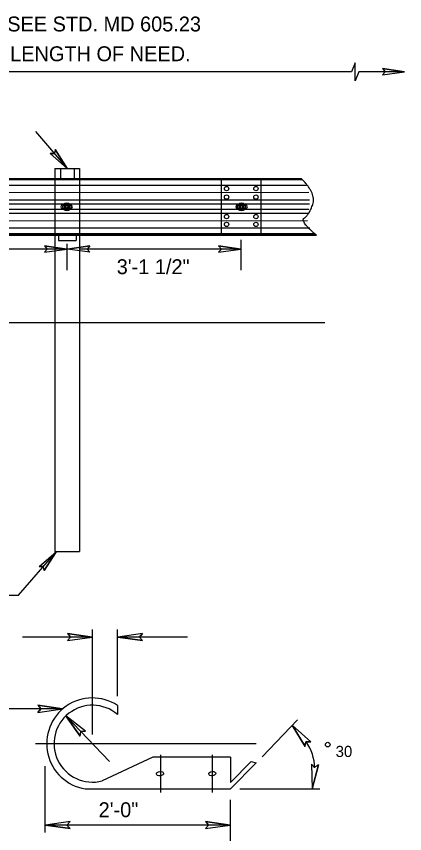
# Model space of a CAD drawing. Extents: x 12.2 to 54.5, y -7.8 to 16.1.
# Drawn here: x 17.698 to 19.261, y 12.576 to 15.871 of the extents above; entities that cross this region are included whole.
import ezdxf

# ---------------------------------------------------------------- set-up
doc = ezdxf.new("R2010")
doc.units = 0
for name, color, linetype in [('BORD-LINE', 7, 'Continuous'), ('DETL-DIMS', 7, 'Continuous'), ('DETL-LINE', 7, 'Continuous'), ('DETL-NOTE', 7, 'Continuous')]:
    doc.layers.add(name, color=color, linetype=linetype)

msp = doc.modelspace()

# ---------------------------------------------------------------- linework, layer by layer
at = {"layer": 'BORD-LINE'}
for p, q in [((17.8531, 15.258), (17.8531, 15.2157)), ((17.8531, 15.258), (17.952, 15.258)), ((17.8753, 15.258), (17.8753, 15.2174)), ((17.9313, 15.258), (17.9313, 15.2162)), ((17.9516, 15.258), (17.9516, 15.2174)), ((17.8531, 15.2247), (17.8531, 14.9901)), ((17.9515, 15.2247), (17.9515, 14.9901)), ((18.8504, 15.2118), (16.7003, 15.2118)), ((18.8462, 15.2162), (16.701, 15.216)), ((18.8758, 15.1602), (16.6898, 15.1599)), ((18.8663, 15.1891), (16.6947, 15.1888)), ((18.8788, 15.13), (16.6823, 15.1297)), ((18.8752, 15.0928), (16.6747, 15.0925)), ((18.8785, 15.1135), (16.6793, 15.1131)), ((17.9167, 15.1102), (17.8839, 15.1102)), ((17.8839, 15.0961), (17.9167, 15.0961)), ((17.8905, 15.1089), (17.8905, 15.0974)), ((17.9116, 15.0974), (17.9116, 15.1089)), ((18.6213, 15.1098), (18.5885, 15.1098)), ((18.5885, 15.0958), (18.6213, 15.0958)), ((18.5938, 15.1086), (18.5938, 15.0971)), ((18.6149, 15.0971), (18.6149, 15.1086)), ((18.8725, 15.0763), (16.6708, 15.076)), ((18.8704, 15.046), (16.6643, 15.0457)), ((18.8992, 14.9945), (16.6539, 14.9942)), ((18.8799, 15.0172), (16.6586, 15.0169)), ((18.906, 14.988), (16.6522, 14.9875)), ((18.9034, 14.9903), (16.6525, 14.99)), ((17.8531, 14.9901), (17.8531, 14.6373)), ((17.8673, 14.9879), (17.8673, 14.9678)), ((17.8673, 14.9678), (17.9388, 14.9678)), ((17.9387, 14.9877), (17.9387, 14.9678)), ((17.9515, 14.9901), (17.9515, 14.6369)), ((12.3965, 14.6369), (18.9405, 14.6369)), ((17.8531, 14.636), (17.8531, 13.713)), ((17.9515, 14.6369), (17.9515, 13.713)), ((17.8531, 13.713), (17.9515, 13.713))]:
    msp.add_line(p, q, dxfattribs=at)
for points in [[(17.901, 15.109), (17.8994, 15.1089), (17.8978, 15.1087), (17.8964, 15.1082), (17.895, 15.1077), (17.8939, 15.1069), (17.8929, 15.1061), (17.8922, 15.1052), (17.8918, 15.1042), (17.8917, 15.1032), (17.8918, 15.1022), (17.8922, 15.1012), (17.8929, 15.1002), (17.8939, 15.0994), (17.895, 15.0987), (17.8964, 15.0981), (17.8978, 15.0977), (17.8994, 15.0974), (17.901, 15.0973)], [(17.901, 15.0973), (17.9027, 15.0974), (17.9042, 15.0977), (17.9057, 15.0981), (17.9071, 15.0987), (17.9082, 15.0994), (17.9091, 15.1002), (17.9098, 15.1012), (17.9103, 15.1022), (17.9104, 15.1032), (17.9103, 15.1042), (17.9098, 15.1052), (17.9091, 15.1061), (17.9082, 15.1069), (17.9071, 15.1077), (17.9057, 15.1082), (17.9042, 15.1087), (17.9027, 15.1089), (17.901, 15.109)], [(18.6043, 15.1087), (18.6027, 15.1086), (18.6011, 15.1083), (18.5996, 15.1079), (18.5983, 15.1073), (18.5972, 15.1066), (18.5962, 15.1057), (18.5955, 15.1048), (18.5951, 15.1038), (18.595, 15.1028), (18.5951, 15.1018), (18.5955, 15.1008), (18.5962, 15.0999), (18.5972, 15.0991), (18.5983, 15.0983), (18.5996, 15.0978), (18.6011, 15.0973), (18.6027, 15.0971), (18.6043, 15.097)], [(18.6043, 15.097), (18.606, 15.0971), (18.6075, 15.0973), (18.609, 15.0978), (18.6103, 15.0983), (18.6115, 15.0991), (18.6124, 15.0999), (18.6131, 15.1008), (18.6136, 15.1018), (18.6137, 15.1028), (18.6136, 15.1038), (18.6131, 15.1048), (18.6124, 15.1057), (18.6115, 15.1066), (18.6103, 15.1073), (18.609, 15.1079), (18.6075, 15.1083), (18.606, 15.1086), (18.6043, 15.1087)]]:
    msp.add_lwpolyline(points, dxfattribs=at)
for centre, radius in [((17.901, 15.1032), 0.0164), ((17.901, 15.1032), 0.00702), ((17.901, 15.1032), 0.00614), ((17.901, 15.1032), 0.00585), ((17.901, 15.1032), 0.00498), ((18.6043, 15.1028), 0.0164), ((18.6043, 15.1028), 0.00702), ((18.6043, 15.1028), 0.00614), ((18.6043, 15.1028), 0.00585), ((18.6043, 15.1028), 0.00498)]:
    msp.add_circle(centre, radius, dxfattribs=at)
for centre, radius, start, end in [((17.8839, 15.1032), 0.00702, 90.0039, 269.9961), ((17.901, 15.1032), 0.012, 28.6537, 151.3463), ((17.901, 15.1032), 0.012, 208.653, 331.347), ((17.901, 15.1032), 0.00879, 120.0035, 179.9936), ((17.901, 15.1032), 0.00879, 180.0054, 239.9976), ((17.901, 15.1032), 0.00878, 59.9996, 120.0004), ((17.901, 15.1032), 0.00878, 239.9975, 300.0025), ((17.901, 15.1032), 0.00643, 57.8729, 122.1271), ((17.901, 15.1032), 0.00643, 237.8729, 302.1271), ((17.901, 15.1032), 0.00879, 0.0064, 59.9965), ((17.901, 15.1032), 0.00879, 300.0024, 359.9946), ((17.9167, 15.1032), 0.00702, 270.0039, 89.9961), ((18.5885, 15.1028), 0.00702, 90.0039, 269.9961), ((18.6043, 15.1028), 0.012, 28.6537, 151.3463), ((18.6043, 15.1028), 0.012, 208.653, 331.347), ((18.6043, 15.1028), 0.00879, 120.0035, 179.9936), ((18.6043, 15.1028), 0.00879, 180.0054, 239.9976), ((18.6043, 15.1028), 0.00878, 59.9996, 120.0004), ((18.6043, 15.1028), 0.00878, 239.9975, 300.0025), ((18.6043, 15.1028), 0.00643, 57.8729, 122.1271), ((18.6043, 15.1028), 0.00643, 237.8729, 302.1271), ((18.6043, 15.1028), 0.00879, 0.0064, 59.9965), ((18.6043, 15.1028), 0.00879, 300.0024, 359.9946), ((18.6213, 15.1028), 0.00702, 270.0039, 89.9961)]:
    msp.add_arc(centre, radius, start, end, dxfattribs=at)
for points in [[(17.8923, 15.1082), (17.8929, 15.1086), (17.8944, 15.1095), (17.8959, 15.1103), (17.8966, 15.1108), (17.8966, 15.1108)], [(17.8923, 15.1082), (17.8923, 15.1078), (17.8923, 15.1068), (17.8923, 15.1051), (17.8923, 15.1038), (17.8923, 15.1032)], [(17.8923, 15.1032), (17.8923, 15.1031), (17.8923, 15.1023), (17.8923, 15.1009), (17.8923, 15.0993), (17.8923, 15.0984), (17.8923, 15.0981)], [(17.8966, 15.0956), (17.896, 15.0959), (17.8948, 15.0966), (17.8933, 15.0975), (17.8925, 15.098), (17.8923, 15.0981)], [(17.8966, 15.1108), (17.8973, 15.1111), (17.8985, 15.1118), (17.8999, 15.1127), (17.9008, 15.1132), (17.901, 15.1133)], [(17.901, 15.093), (17.9003, 15.0934), (17.8989, 15.0943), (17.8974, 15.0951), (17.8967, 15.0955), (17.8966, 15.0956)], [(17.901, 15.1133), (17.9017, 15.1129), (17.9032, 15.1121), (17.9046, 15.1112), (17.9054, 15.1108), (17.9054, 15.1108)], [(17.9054, 15.0956), (17.9048, 15.0952), (17.9036, 15.0945), (17.9021, 15.0937), (17.9013, 15.0932), (17.901, 15.093)], [(17.9054, 15.1108), (17.906, 15.1104), (17.9073, 15.1097), (17.9087, 15.1089), (17.9096, 15.1084), (17.9098, 15.1082)], [(17.9098, 15.0981), (17.9091, 15.0977), (17.9077, 15.0969), (17.9062, 15.096), (17.9054, 15.0956), (17.9054, 15.0956)], [(17.9098, 15.1082), (17.9098, 15.1078), (17.9098, 15.1068), (17.9098, 15.1051), (17.9098, 15.1038), (17.9098, 15.1032)], [(17.9098, 15.1032), (17.9098, 15.1031), (17.9098, 15.1023), (17.9098, 15.1009), (17.9098, 15.0993), (17.9098, 15.0984), (17.9098, 15.0981)], [(18.5955, 15.1079), (18.5962, 15.1083), (18.5977, 15.1091), (18.5991, 15.11), (18.5999, 15.1104), (18.5999, 15.1104)], [(18.5955, 15.1079), (18.5955, 15.1075), (18.5955, 15.1064), (18.5955, 15.1047), (18.5955, 15.1035), (18.5955, 15.1028)], [(18.5955, 15.1028), (18.5955, 15.1027), (18.5955, 15.1019), (18.5955, 15.1006), (18.5955, 15.099), (18.5955, 15.098), (18.5955, 15.0978)], [(18.5999, 15.0952), (18.5993, 15.0956), (18.5981, 15.0963), (18.5966, 15.0971), (18.5958, 15.0976), (18.5955, 15.0978)], [(18.5999, 15.1104), (18.6005, 15.1108), (18.6018, 15.1115), (18.6032, 15.1123), (18.6041, 15.1128), (18.6043, 15.113)], [(18.6043, 15.0927), (18.6036, 15.0931), (18.6022, 15.0939), (18.6007, 15.0948), (18.6, 15.0952), (18.5999, 15.0952)], [(18.6043, 15.113), (18.605, 15.1126), (18.6065, 15.1117), (18.6079, 15.1109), (18.6087, 15.1104), (18.6087, 15.1104)], [(18.6087, 15.0952), (18.6081, 15.0949), (18.6069, 15.0942), (18.6054, 15.0933), (18.6046, 15.0928), (18.6043, 15.0927)], [(18.6087, 15.1104), (18.6093, 15.1101), (18.6106, 15.1094), (18.612, 15.1085), (18.6129, 15.108), (18.6131, 15.1079)], [(18.6131, 15.0978), (18.6124, 15.0974), (18.611, 15.0965), (18.6095, 15.0957), (18.6087, 15.0952), (18.6087, 15.0952)], [(18.6131, 15.1079), (18.6131, 15.1075), (18.6131, 15.1064), (18.6131, 15.1047), (18.6131, 15.1035), (18.6131, 15.1028)], [(18.6131, 15.1028), (18.6131, 15.1027), (18.6131, 15.1019), (18.6131, 15.1006), (18.6131, 15.099), (18.6131, 15.098), (18.6131, 15.0978)]]:
    msp.add_open_spline(points, degree=3, dxfattribs=at)
at = {"layer": 'DETL-DIMS'}
for p, q in [((19.1718, 15.6607), (19.2614, 15.6475)), ((19.1718, 15.6607), (19.1829, 15.6475)), ((19.0481, 15.6475), (15.8393, 15.6475)), ((19.2508, 15.6477), (19.0768, 15.6477)), ((19.1718, 15.6346), (19.2614, 15.6475)), ((19.1718, 15.6346), (19.1829, 15.6475)), ((17.7744, 15.4067), (17.9026, 15.258)), ((17.854, 15.3345), (17.8513, 15.3175)), ((17.854, 15.3345), (17.9026, 15.258)), ((17.8343, 15.3175), (17.9026, 15.258)), ((17.8343, 15.3175), (17.8513, 15.3175)), ((18.5234, 14.989), (18.5234, 15.2162)), ((18.6832, 14.988), (18.6832, 15.2152)), ((18.6038, 14.8471), (18.6038, 14.9706)), ((17.9011, 14.9328), (16.5563, 14.9328)), ((17.8115, 14.946), (17.9011, 14.9328)), ((17.8115, 14.946), (17.8226, 14.9328)), ((17.8115, 14.9199), (17.9011, 14.9328)), ((17.8115, 14.9199), (17.8226, 14.9328)), ((17.903, 14.8471), (17.903, 14.9532)), ((17.9936, 14.946), (17.904, 14.9328)), ((17.9936, 14.9199), (17.904, 14.9328)), ((18.5841, 14.9328), (17.9563, 14.9328)), ((17.9936, 14.946), (17.9825, 14.9328)), ((17.9936, 14.9199), (17.9825, 14.9328)), ((18.5123, 14.946), (18.6019, 14.9328)), ((18.5123, 14.946), (18.5234, 14.9328)), ((18.5123, 14.9199), (18.6019, 14.9328)), ((18.5123, 14.9199), (18.5234, 14.9328)), ((17.707, 13.5375), (17.858, 13.7127)), ((17.7897, 13.6532), (17.858, 13.7127)), ((17.8095, 13.6362), (17.858, 13.7127)), ((17.7897, 13.6532), (17.8068, 13.6532)), ((17.8095, 13.6362), (17.8068, 13.6532)), ((17.5585, 13.5375), (17.707, 13.5375)), ((17.9038, 13.383), (18.0027, 13.3686)), ((17.9038, 13.383), (17.9162, 13.3686)), ((17.9038, 13.383), (18.0027, 13.3686)), ((17.9038, 13.383), (17.9162, 13.3686)), ((18.0045, 12.9761), (18.0045, 13.3986)), ((18.0045, 12.9761), (18.0045, 13.3986)), ((18.1058, 13.1306), (18.1058, 13.3986)), ((18.1058, 13.1306), (18.1058, 13.3986)), ((18.2057, 13.383), (18.1068, 13.3686)), ((18.2057, 13.383), (18.1068, 13.3686)), ((18.2057, 13.383), (18.1934, 13.3686)), ((18.2057, 13.383), (18.1934, 13.3686)), ((18.0027, 13.3686), (17.7225, 13.3686)), ((18.0027, 13.3686), (17.7225, 13.3686)), ((17.9038, 13.3542), (18.0027, 13.3686)), ((17.9038, 13.3542), (17.9162, 13.3686)), ((17.9038, 13.3542), (18.0027, 13.3686)), ((17.9038, 13.3542), (17.9162, 13.3686)), ((18.387, 13.3686), (18.1068, 13.3686)), ((18.2057, 13.3542), (18.1068, 13.3686)), ((18.387, 13.3686), (18.1068, 13.3686)), ((18.2057, 13.3542), (18.1068, 13.3686)), ((18.2057, 13.3542), (18.1934, 13.3686)), ((18.2057, 13.3542), (18.1934, 13.3686)), ((17.7845, 13.0935), (17.8835, 13.0791)), ((17.7845, 13.0935), (17.7971, 13.0791)), ((17.8835, 13.0791), (17.2601, 13.0791)), ((17.7845, 13.0647), (17.8835, 13.0791)), ((17.7845, 13.0647), (17.7971, 13.0791)), ((17.8975, 13.0507), (18.0726, 12.8672)), ((17.8975, 13.0507), (18.0726, 12.8672)), ((17.9552, 12.9692), (17.8975, 13.0507)), ((17.9762, 12.9891), (17.8975, 13.0507)), ((18.6878, 12.8862), (18.8294, 13.0344)), ((18.6878, 12.8862), (18.8294, 13.0344)), ((17.9552, 12.9692), (17.9571, 12.9881)), ((17.9762, 12.9891), (17.9571, 12.9881)), ((18.8612, 12.9277), (18.8087, 13.0127)), ((18.8834, 12.9464), (18.8087, 13.0127)), ((18.8612, 12.9277), (18.8087, 13.0127)), ((18.8834, 12.9464), (18.8087, 13.0127)), ((18.6639, 12.9386), (17.7751, 12.9386)), ((18.6639, 12.9386), (17.7751, 12.9386)), ((18.8612, 12.9277), (18.8642, 12.9466)), ((18.8612, 12.9277), (18.8642, 12.9466)), ((18.8834, 12.9464), (18.8642, 12.9466)), ((18.8834, 12.9464), (18.8642, 12.9466)), ((18.2781, 12.8932), (18.2781, 12.7415)), ((18.2781, 12.8932), (18.2781, 12.7415)), ((18.4868, 12.8932), (18.4868, 12.7415)), ((18.4868, 12.8932), (18.4868, 12.7415)), ((18.8859, 12.8561), (18.8894, 12.7565)), ((18.8859, 12.8561), (18.899, 12.8424)), ((18.8859, 12.8561), (18.8894, 12.7565)), ((18.8859, 12.8561), (18.899, 12.8424)), ((18.9147, 12.8531), (18.8894, 12.7565)), ((18.9147, 12.8531), (18.8894, 12.7565)), ((18.9147, 12.8531), (18.899, 12.8424)), ((18.9147, 12.8531), (18.899, 12.8424)), ((17.8124, 12.8486), (17.8124, 12.5804)), ((18.5974, 12.7565), (18.9194, 12.7565)), ((18.5974, 12.7565), (18.9194, 12.7565)), ((18.5583, 12.7121), (18.5583, 12.0215)), ((17.9139, 12.6248), (17.8151, 12.6104)), ((17.9139, 12.6248), (17.9015, 12.6104)), ((18.4595, 12.6248), (18.5583, 12.6104)), ((18.4595, 12.6248), (18.4719, 12.6104)), ((18.5583, 12.6104), (17.8151, 12.6104)), ((17.9139, 12.596), (17.8151, 12.6104)), ((17.9139, 12.596), (17.9015, 12.6104)), ((18.4595, 12.596), (18.5583, 12.6104)), ((18.4595, 12.596), (18.4719, 12.6104))]:
    msp.add_line(p, q, dxfattribs=at)
for points in [[(19.1718, 15.6346), (19.2614, 15.6475), (19.1718, 15.6607), (19.1829, 15.6475)], [(17.8343, 15.3175), (17.9026, 15.258), (17.854, 15.3345), (17.8513, 15.3175)], [(17.8115, 14.9199), (17.9011, 14.9328), (17.8115, 14.946), (17.8226, 14.9328)], [(17.9936, 14.9199), (17.904, 14.9328), (17.9936, 14.946), (17.9825, 14.9328)], [(18.5123, 14.9199), (18.6019, 14.9328), (18.5123, 14.946), (18.5234, 14.9328)], [(17.7897, 13.6532), (17.858, 13.7127), (17.8095, 13.6362), (17.8068, 13.6532)], [(17.9038, 13.3542), (18.0027, 13.3686), (17.9038, 13.383), (17.9162, 13.3686)], [(17.9038, 13.3542), (18.0027, 13.3686), (17.9038, 13.383), (17.9162, 13.3686)], [(18.2057, 13.383), (18.1068, 13.3686), (18.2057, 13.3542), (18.1934, 13.3686)], [(18.2057, 13.383), (18.1068, 13.3686), (18.2057, 13.3542), (18.1934, 13.3686)], [(17.7845, 13.0647), (17.8835, 13.0791), (17.7845, 13.0935), (17.7971, 13.0791)], [(17.9762, 12.9891), (17.8975, 13.0507), (17.9552, 12.9692), (17.9571, 12.9881)], [(18.8834, 12.9464), (18.8087, 13.0127), (18.8612, 12.9277), (18.8642, 12.9466)], [(18.8834, 12.9464), (18.8087, 13.0127), (18.8612, 12.9277), (18.8642, 12.9466)], [(18.8859, 12.8561), (18.8894, 12.7565), (18.9147, 12.8531), (18.899, 12.8424)], [(18.8859, 12.8561), (18.8894, 12.7565), (18.9147, 12.8531), (18.899, 12.8424)], [(17.9139, 12.6248), (17.8151, 12.6104), (17.9139, 12.596), (17.9015, 12.6104)], [(18.4595, 12.596), (18.5583, 12.6104), (18.4595, 12.6248), (18.4719, 12.6104)]]:
    msp.add_lwpolyline(points, close=True, dxfattribs=at)
msp.add_arc((18.712, 12.8382), 0.1871, 0.8426, 35.4564, dxfattribs=at)
msp.add_arc((18.712, 12.8382), 0.1871, 0.8426, 35.4564, dxfattribs=at)
at = {"layer": 'DETL-LINE'}
for p, q in [((19.0626, 15.6834), (19.0481, 15.6475)), ((19.0626, 15.6116), (19.0626, 15.6834)), ((19.0771, 15.6475), (19.0626, 15.6116)), ((18.1051, 13.093), (18.1051, 13.0566)), ((18.2472, 12.8843), (18.0428, 12.7883)), ((18.2472, 12.8843), (18.0428, 12.7883)), ((18.5603, 12.8843), (18.2472, 12.8843)), ((18.5603, 12.8843), (18.2472, 12.8843)), ((18.5603, 12.8843), (18.5603, 12.7824)), ((18.5603, 12.8843), (18.5603, 12.7824)), ((18.5599, 12.7565), (18.6639, 12.8612)), ((18.5599, 12.7565), (18.6639, 12.8612)), ((18.5603, 12.7824), (18.6438, 12.8662)), ((18.5603, 12.7824), (18.6438, 12.8662)), ((18.6438, 12.8662), (18.6639, 12.8612)), ((18.6438, 12.8662), (18.6639, 12.8612)), ((17.9751, 12.7565), (18.5599, 12.7565)), ((17.9751, 12.7565), (18.5599, 12.7565))]:
    msp.add_line(p, q, dxfattribs=at)
for centre in [(18.5442, 15.1765), (18.6625, 15.1765), (18.5442, 15.1421), (18.6625, 15.1421), (18.5442, 15.0637), (18.6625, 15.0637), (18.5442, 15.0323), (18.6625, 15.0323)]:
    msp.add_circle(centre, 0.00883, dxfattribs=at)
for radius, start, end in [(0.1844, 56.9361, 260.8208), (0.1844, 56.9361, 260.8208), (0.155, 49.55, 284.315), (0.155, 49.55, 284.315)]:
    msp.add_arc((18.0045, 12.9386), radius, start, end, dxfattribs=at)
for centre in [(18.2763, 12.8173), (18.2763, 12.8173), (18.4868, 12.8173), (18.4868, 12.8173)]:
    msp.add_ellipse(centre, major_axis=(-0.0144, -0.0017), ratio=0.601104, dxfattribs=at)
msp.add_open_spline([(18.9064, 14.9881), (18.8387, 15.0461), (18.8758, 15.0693), (18.9068, 15.1555), (18.8463, 15.216)], degree=2, dxfattribs=at)
at = {"layer": 'DETL-NOTE'}
msp.add_circle((18.9518, 12.9347), 0.00937, dxfattribs=at)

# ---------------------------------------------------------------- texts
for s, height, p in [('BEGIN STANDARD TRAFFIC BARRIER W-BEAM. SEE STD. MD 605.23', 0.06, (15.8111, 15.8101)), ('25\'-0" MINIMUM TO DOWNSTREAM END OF LENGTH OF NEED. ', 0.06, (15.9932, 15.6901)), ('3\'-1 1/2"', 0.06, (18.102, 14.8316)), ('30', 0.045, (18.9835, 12.8849)), ('2\'-0"', 0.06, (18.0293, 12.6423))]:
    msp.add_text(s, height=height, dxfattribs=at).set_placement(p)

doc.saveas('drawing.dxf')
